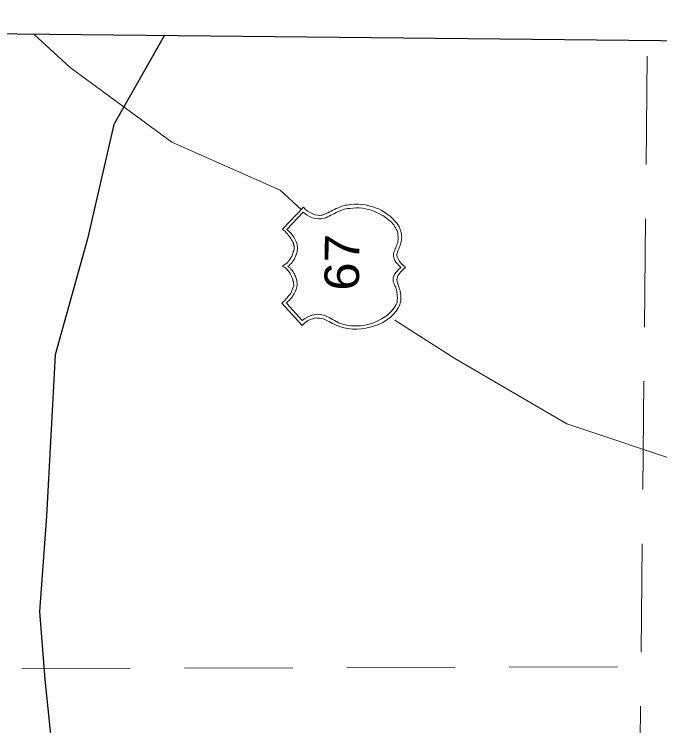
# Model space of a CAD drawing. Extents: x 2356576 to 2377878, y 6966390 to 6990634.
# Drawn here: x 2365982.5 to 2366109.4, y 6969120 to 6969259.9 of the extents above; entities that cross this region are included whole.
import ezdxf

# ---------------------------------------------------------------- set-up
doc = ezdxf.new("R2010")
doc.units = 0
doc.header["$LTSCALE"] = 7.1
doc.linetypes.add('MEDIUM_DASHED', pattern=[4.5, 3, -1.5])
doc.layers.add('19', color=7, linetype='Continuous', lineweight=13)
doc.layers.add('8', color=7, linetype='Continuous', lineweight=13)

msp = doc.modelspace()

# ---------------------------------------------------------------- linework, layer by layer
at = {"layer": '19', "linetype": 'MEDIUM_DASHED'}
for p, q in [((2366100.797, 6968655.28), (2366107.007, 6969254.676)), ((2365728.404, 6969130.515), (2366103.06, 6969131.614))]:
    msp.add_line(p, q, dxfattribs=at)
at = {"layer": '19'}
msp.add_line((2366034.755, 6969225.33), (2366038.887, 6969221.475), dxfattribs=at)
at = {"layer": '19', "lineweight": 25}
for points in [[(2365597.072, 6968660.498), (2366217.375, 6968654.072), (2366223.585, 6969253.468), (2365603.282, 6969259.894)], [(2366011.996, 6969255.66), (2366002.067, 6969238.242), (2365996.913, 6969215.73), (2365990.557, 6969192.935), (2365988.816, 6969161.211), (2365987.454, 6969142.5), (2365988.484, 6969129.141), (2365990.827, 6969106.283), (2365990.663, 6969090.412), (2365991.32, 6969078.497)]]:
    msp.add_lwpolyline(points, dxfattribs=at)
at = {"layer": '19'}
for points in [[(2365986.377, 6969255.925), (2365993.45, 6969249.432), (2366013.459, 6969234.732), (2366034.755, 6969225.33)], [(2366039.1, 6969198.732), (2366035.125, 6969203.125), (2366035.399, 6969203.363), (2366035.67, 6969203.6), (2366035.885, 6969203.866), (2366036.127, 6969204.103), (2366036.31, 6969204.341), (2366036.492, 6969204.611), (2366036.675, 6969204.817), (2366036.857, 6969205.088), (2366037.008, 6969205.326), (2366037.102, 6969205.565), (2366037.225, 6969205.832), (2366037.288, 6969206.071), (2366037.378, 6969206.342), (2366037.441, 6969206.55), (2366037.443, 6969206.822), (2366037.418, 6969207.09), (2366037.388, 6969207.27), (2366037.302, 6969207.483), (2366037.273, 6969207.723), (2366037.215, 6969207.964), (2366037.098, 6969208.205), (2366037.012, 6969208.414), (2366036.894, 6969208.655), (2366036.777, 6969208.897), (2366036.599, 6969209.138), (2366036.449, 6969209.352), (2366036.244, 6969209.562), (2366036.126, 6969209.775), (2366035.888, 6969209.958), (2366035.677, 6969210.108), (2366035.439, 6969210.231), (2366035.2, 6969210.353), (2366035.441, 6969210.503), (2366035.683, 6969210.68), (2366035.925, 6969210.826), (2366036.139, 6969211.035), (2366036.349, 6969211.213), (2366036.503, 6969211.452), (2366036.685, 6969211.658), (2366036.836, 6969211.896), (2366036.958, 6969212.135), (2366037.113, 6969212.373), (2366037.204, 6969212.644), (2366037.298, 6969212.883), (2366037.361, 6969213.183), (2366037.451, 6969213.39), (2366037.514, 6969213.689), (2366037.517, 6969213.961), (2366037.519, 6969214.169), (2366037.522, 6969214.409), (2366037.436, 6969214.622), (2366037.379, 6969214.891), (2366037.261, 6969215.104), (2366037.172, 6969215.345), (2366037.026, 6969215.554), (2366036.908, 6969215.796), (2366036.73, 6969216.009), (2366036.553, 6969216.279), (2366036.375, 6969216.493), (2366036.198, 6969216.735), (2366035.96, 6969216.945), (2366035.751, 6969217.22), (2366035.513, 6969217.402), (2366035.275, 6969217.645), (2366039.34, 6969221.951), (2366039.728, 6969221.559), (2366040.172, 6969221.162), (2366040.681, 6969220.889), (2366041.187, 6969220.672), (2366041.697, 6969220.458), (2366042.176, 6969220.393), (2366042.564, 6969220.357), (2366042.836, 6969220.386), (2366043.076, 6969220.412), (2366043.318, 6969220.529), (2366043.586, 6969220.587), (2366043.86, 6969220.736), (2366044.161, 6969220.881), (2366044.463, 6969221.03), (2366044.792, 6969221.174), (2366045.154, 6969221.35), (2366045.488, 6969221.527), (2366045.818, 6969221.704), (2366046.211, 6969221.852), (2366046.541, 6969221.996), (2366046.903, 6969222.144), (2366047.235, 6969222.229), (2366047.565, 6969222.346), (2366047.925, 6969222.374), (2366048.678, 6969222.486), (2366049.427, 6969222.538), (2366050.119, 6969222.531), (2366050.838, 6969222.464), (2366051.525, 6969222.397), (2366052.216, 6969222.237), (2366052.874, 6969222.083), (2366053.532, 6969221.864), (2366054.157, 6969221.617), (2366054.754, 6969221.311)], [(2366055.79, 6969219.74), (2366055.461, 6969219.984), (2366055.075, 6969220.26), (2366054.658, 6969220.472), (2366054.208, 6969220.717), (2366053.73, 6969220.934), (2366053.225, 6969221.147), (2366052.687, 6969221.364), (2366052.148, 6969221.518), (2366051.55, 6969221.644), (2366050.951, 6969221.742), (2366050.351, 6969221.809), (2366049.719, 6969221.815), (2366049.059, 6969221.79), (2366048.49, 6969221.736), (2366047.95, 6969221.682), (2366047.469, 6969221.567), (2366047.015, 6969221.423), (2366046.594, 6969221.276), (2366046.172, 6969221.1), (2366045.81, 6969220.924), (2366045.448, 6969220.719), (2366045.086, 6969220.511), (2366044.756, 6969220.367), (2366044.422, 6969220.19), (2366044.093, 6969220.041), (2366043.759, 6969219.897), (2366043.43, 6969219.808), (2366043.129, 6969219.723), (2366042.769, 6969219.667), (2366042.349, 6969219.671), (2366041.869, 6969219.736), (2366041.418, 6969219.829), (2366040.972, 6969219.954), (2366040.521, 6969220.138), (2366040.104, 6969220.415), (2366039.719, 6969220.687), (2366039.33, 6969220.991), (2366036.115, 6969217.604), (2366036.325, 6969217.394), (2366036.531, 6969217.212), (2366036.769, 6969216.997), (2366036.947, 6969216.787), (2366037.124, 6969216.545), (2366037.302, 6969216.304), (2366037.451, 6969216.062), (2366037.597, 6969215.82), (2366037.714, 6969215.547), (2366037.863, 6969215.306), (2366037.98, 6969215.036), (2366038.038, 6969214.824), (2366038.095, 6969214.555), (2366038.121, 6969214.343), (2366038.179, 6969214.162), (2366038.177, 6969213.954), (2366038.175, 6969213.742), (2366038.144, 6969213.475), (2366038.11, 6969213.235), (2366038.079, 6969212.995), (2366037.984, 6969212.724), (2366037.894, 6969212.517), (2366037.8, 6969212.246), (2366037.677, 6969212.007), (2366037.587, 6969211.8), (2366037.432, 6969211.502), (2366037.282, 6969211.323), (2366037.128, 6969211.113), (2366036.945, 6969210.875), (2366036.736, 6969210.729), (2366036.554, 6969210.519), (2366036.28, 6969210.342), (2366036.518, 6969210.159), (2366036.728, 6969210.009), (2366036.906, 6969209.795), (2366037.052, 6969209.614), (2366037.202, 6969209.432), (2366037.32, 6969209.251), (2366037.466, 6969209.009), (2366037.616, 6969208.86), (2366037.674, 6969208.619), (2366037.792, 6969208.406), (2366037.85, 6969208.197), (2366037.935, 6969207.985), (2366037.965, 6969207.776), (2366038.051, 6969207.535), (2366038.081, 6969207.323), (2366038.106, 6969207.115), (2366038.136, 6969206.874), (2366038.133, 6969206.574), (2366038.07, 6969206.335), (2366038.007, 6969206.036), (2366037.912, 6969205.765), (2366037.789, 6969205.466), (2366037.666, 6969205.167), (2366037.516, 6969204.961), (2366037.361, 6969204.662), (2366037.21, 6969204.392), (2366037.028, 6969204.154), (2366036.814, 6969203.948), (2366036.631, 6969203.678), (2366036.389, 6969203.472)], [(2366054.754, 6969221.311), (2366055.323, 6969220.977), (2366055.859, 6969220.612), (2366056.395, 6969220.214), (2366056.898, 6969219.729), (2366057.345, 6969219.244), (2366057.788, 6969218.731), (2366057.997, 6969218.429), (2366058.174, 6969218.127), (2366058.318, 6969217.826), (2366058.407, 6969217.525), (2366058.525, 6969217.252), (2366058.581, 6969216.951), (2366058.638, 6969216.623), (2366058.663, 6969216.35), (2366058.692, 6969216.05), (2366058.657, 6969215.75), (2366058.654, 6969215.482), (2366058.591, 6969215.211), (2366058.5, 6969214.912), (2366058.466, 6969214.672), (2366058.375, 6969214.433), (2366058.281, 6969214.194), (2366058.19, 6969213.955), (2366058.096, 6969213.748), (2366057.974, 6969213.537), (2366057.912, 6969213.33), (2366057.85, 6969213.119), (2366057.787, 6969212.879), (2366057.757, 6969212.671), (2366057.755, 6969212.431), (2366057.812, 6969212.191), (2366057.898, 6969211.95), (2366058.047, 6969211.676), (2366058.192, 6969211.435), (2366058.429, 6969211.104), (2366058.666, 6969210.802), (2366059.023, 6969210.498), (2366059.41, 6969210.102), (2366059.047, 6969209.778), (2366058.744, 6969209.449), (2366058.441, 6969209.184), (2366058.258, 6969208.914), (2366058.076, 6969208.676), (2366057.921, 6969208.438), (2366057.859, 6969208.23), (2366057.769, 6969208.019), (2366057.735, 6969207.839), (2366057.733, 6969207.631), (2366057.763, 6969207.479), (2366057.821, 6969207.271), (2366057.847, 6969207.09), (2366057.905, 6969206.91), (2366057.995, 6969206.697), (2366058.053, 6969206.488), (2366058.139, 6969206.335), (2366058.197, 6969206.095), (2366058.286, 6969205.854), (2366058.372, 6969205.613), (2366058.401, 6969205.344), (2366058.459, 6969205.104), (2366058.516, 6969204.803), (2366058.541, 6969204.563), (2366058.538, 6969204.263), (2366058.535, 6969204.023), (2366058.532, 6969203.723), (2366058.501, 6969203.391), (2366058.406, 6969203.124), (2366058.343, 6969202.825), (2366058.22, 6969202.526), (2366058.069, 6969202.228), (2366057.61, 6969201.54), (2366057.035, 6969200.886), (2366056.397, 6969200.293), (2366055.703, 6969199.76), (2366054.946, 6969199.288), (2366054.194, 6969198.908), (2366053.351, 6969198.616), (2366052.476, 6969198.353), (2366051.635, 6969198.182), (2366050.765, 6969198.043), (2366049.865, 6969197.992), (2366048.993, 6969198.001), (2366048.094, 6969198.099), (2366047.287, 6969198.259), (2366046.45, 6969198.508), (2366045.673, 6969198.816), (2366045.374, 6969198.939), (2366045.076, 6969199.09), (2366044.746, 6969199.274), (2366044.42, 6969199.489), (2366044.061, 6969199.641), (2366043.703, 6969199.824), (2366043.313, 6969200.008), (2366042.926, 6969200.072), (2366042.507, 6969200.169), (2366042.055, 6969200.173), (2366041.635, 6969200.178), (2366041.153, 6969200.031), (2366040.672, 6969199.888), (2366040.129, 6969199.593)], [(2366035.997, 6969203.116), (2366039.109, 6969199.664), (2366039.625, 6969200.047), (2366040.108, 6969200.314), (2366040.559, 6969200.549), (2366040.98, 6969200.725), (2366041.433, 6969200.808), (2366041.822, 6969200.896), (2366042.183, 6969200.952), (2366042.574, 6969200.888), (2366042.961, 6969200.792), (2366043.321, 6969200.728), (2366043.711, 6969200.604), (2366044.069, 6969200.421), (2366044.396, 6969200.269), (2366044.754, 6969200.085), (2366045.084, 6969199.87), (2366045.442, 6969199.658), (2366046.245, 6969199.258), (2366047.083, 6969198.981), (2366047.892, 6969198.761), (2366048.759, 6969198.664), (2366049.659, 6969198.623), (2366050.559, 6969198.645), (2366051.433, 6969198.784), (2366052.275, 6969198.988), (2366053.146, 6969199.247), (2366053.961, 6969199.598), (2366054.745, 6969199.982), (2366055.47, 6969200.455), (2366056.076, 6969200.956), (2366056.709, 6969201.522), (2366057.196, 6969202.145), (2366057.623, 6969202.8), (2366057.656, 6969202.952), (2366057.746, 6969203.099), (2366057.808, 6969203.31), (2366057.811, 6969203.55), (2366057.812, 6969203.73), (2366057.847, 6969203.97), (2366057.849, 6969204.21), (2366057.82, 6969204.45), (2366057.823, 6969204.718), (2366057.825, 6969204.958), (2366057.74, 6969205.199), (2366057.71, 6969205.44), (2366057.685, 6969205.68), (2366057.595, 6969205.893), (2366057.537, 6969206.101), (2366057.479, 6969206.282), (2366057.361, 6969206.495), (2366057.275, 6969206.676), (2366057.185, 6969206.857), (2366057.127, 6969207.038), (2366057.041, 6969207.279), (2366057.011, 6969207.427), (2366056.985, 6969207.639), (2366056.987, 6969207.847), (2366057.017, 6969208.059), (2366057.08, 6969208.358), (2366057.174, 6969208.565), (2366057.357, 6969208.803), (2366057.508, 6969209.102), (2366057.811, 6969209.399), (2366058.115, 6969209.756), (2366058.51, 6969210.084), (2366058.095, 6969210.508), (2366057.798, 6969210.871), (2366057.529, 6969211.174), (2366057.325, 6969211.504), (2366057.208, 6969211.805), (2366057.118, 6969212.046), (2366057.061, 6969212.319), (2366057.064, 6969212.587), (2366057.099, 6969212.826), (2366057.129, 6969213.038), (2366057.223, 6969213.277), (2366057.314, 6969213.516), (2366057.408, 6969213.755), (2366057.53, 6969213.962), (2366057.621, 6969214.233), (2366057.744, 6969214.5), (2366057.807, 6969214.771), (2366057.93, 6969215.038), (2366057.933, 6969215.338), (2366057.967, 6969215.609), (2366057.999, 6969215.909), (2366057.974, 6969216.209), (2366057.944, 6969216.478), (2366057.92, 6969216.778), (2366057.83, 6969217.051), (2366057.773, 6969217.352), (2366057.596, 6969217.621), (2366057.479, 6969217.923), (2366057.302, 6969218.164), (2366057.125, 6969218.466), (2366056.888, 6969218.741), (2366056.651, 6969219.011), (2366056.413, 6969219.226), (2366056.087, 6969219.469), (2366055.79, 6969219.74)], [(2366036.389, 6969203.472), (2366036.179, 6969203.294), (2366035.997, 6969203.116)], [(2366040.129, 6969199.593), (2366039.617, 6969199.239), (2366039.1, 6969198.732)], [(2366057.323, 6969199.743), (2366069.126, 6969192.209), (2366091.194, 6969179.379), (2366116.101, 6969171.021), (2366135.168, 6969166.623), (2366152.425, 6969144.183), (2366165.834, 6969143.864), (2366178.148, 6969121.955), (2366189.725, 6969104.283), (2366199.135, 6969082.764), (2366204.465, 6969052.823), (2366210.021, 6969027.324), (2366216.934, 6968999.531), (2366220.78, 6968982.778)]]:
    msp.add_lwpolyline(points, dxfattribs=at)
at = {"layer": '8', "linetype": 'MEDIUM_DASHED'}
for p, q in [((2366100.797, 6968655.28), (2366107.007, 6969254.676)), ((2365728.404, 6969130.515), (2366103.06, 6969131.614))]:
    msp.add_line(p, q, dxfattribs=at)
at = {"layer": '8'}
msp.add_line((2366034.755, 6969225.33), (2366038.887, 6969221.475), dxfattribs=at)
at = {"layer": '8', "lineweight": 25}
for points in [[(2365597.072, 6968660.498), (2366217.375, 6968654.072), (2366223.585, 6969253.468), (2365603.282, 6969259.894)], [(2366011.996, 6969255.66), (2366002.067, 6969238.242), (2365996.913, 6969215.73), (2365990.557, 6969192.935), (2365988.816, 6969161.211), (2365987.454, 6969142.5), (2365988.484, 6969129.141), (2365990.827, 6969106.283), (2365990.663, 6969090.412), (2365991.32, 6969078.497)]]:
    msp.add_lwpolyline(points, dxfattribs=at)
at = {"layer": '8'}
for points in [[(2365986.377, 6969255.925), (2365993.45, 6969249.432), (2366013.459, 6969234.732), (2366034.755, 6969225.33)], [(2366039.1, 6969198.732), (2366035.125, 6969203.125), (2366035.399, 6969203.363), (2366035.67, 6969203.6), (2366035.885, 6969203.866), (2366036.127, 6969204.103), (2366036.31, 6969204.341), (2366036.492, 6969204.611), (2366036.675, 6969204.817), (2366036.857, 6969205.088), (2366037.008, 6969205.326), (2366037.102, 6969205.565), (2366037.225, 6969205.832), (2366037.288, 6969206.071), (2366037.378, 6969206.342), (2366037.441, 6969206.55), (2366037.443, 6969206.822), (2366037.418, 6969207.09), (2366037.388, 6969207.27), (2366037.302, 6969207.483), (2366037.273, 6969207.723), (2366037.215, 6969207.964), (2366037.098, 6969208.205), (2366037.012, 6969208.414), (2366036.894, 6969208.655), (2366036.777, 6969208.897), (2366036.599, 6969209.138), (2366036.449, 6969209.352), (2366036.244, 6969209.562), (2366036.126, 6969209.775), (2366035.888, 6969209.958), (2366035.677, 6969210.108), (2366035.439, 6969210.231), (2366035.2, 6969210.353), (2366035.441, 6969210.503), (2366035.683, 6969210.68), (2366035.925, 6969210.826), (2366036.139, 6969211.035), (2366036.349, 6969211.213), (2366036.503, 6969211.452), (2366036.685, 6969211.658), (2366036.836, 6969211.896), (2366036.958, 6969212.135), (2366037.113, 6969212.373), (2366037.204, 6969212.644), (2366037.298, 6969212.883), (2366037.361, 6969213.183), (2366037.451, 6969213.39), (2366037.514, 6969213.689), (2366037.517, 6969213.961), (2366037.519, 6969214.169), (2366037.522, 6969214.409), (2366037.436, 6969214.622), (2366037.379, 6969214.891), (2366037.261, 6969215.104), (2366037.172, 6969215.345), (2366037.026, 6969215.554), (2366036.908, 6969215.796), (2366036.73, 6969216.009), (2366036.553, 6969216.279), (2366036.375, 6969216.493), (2366036.198, 6969216.735), (2366035.96, 6969216.945), (2366035.751, 6969217.22), (2366035.513, 6969217.402), (2366035.275, 6969217.645), (2366039.34, 6969221.951), (2366039.728, 6969221.559), (2366040.172, 6969221.162), (2366040.681, 6969220.889), (2366041.187, 6969220.672), (2366041.697, 6969220.458), (2366042.176, 6969220.393), (2366042.564, 6969220.357), (2366042.836, 6969220.386), (2366043.076, 6969220.412), (2366043.318, 6969220.529), (2366043.586, 6969220.587), (2366043.86, 6969220.736), (2366044.161, 6969220.881), (2366044.463, 6969221.03), (2366044.792, 6969221.174), (2366045.154, 6969221.35), (2366045.488, 6969221.527), (2366045.818, 6969221.704), (2366046.211, 6969221.852), (2366046.541, 6969221.996), (2366046.903, 6969222.144), (2366047.235, 6969222.229), (2366047.565, 6969222.346), (2366047.925, 6969222.374), (2366048.678, 6969222.486), (2366049.427, 6969222.538), (2366050.119, 6969222.531), (2366050.838, 6969222.464), (2366051.525, 6969222.397), (2366052.216, 6969222.237), (2366052.874, 6969222.083), (2366053.532, 6969221.864), (2366054.157, 6969221.617), (2366054.754, 6969221.311)], [(2366055.79, 6969219.74), (2366055.461, 6969219.984), (2366055.075, 6969220.26), (2366054.658, 6969220.472), (2366054.208, 6969220.717), (2366053.73, 6969220.934), (2366053.225, 6969221.147), (2366052.687, 6969221.364), (2366052.148, 6969221.518), (2366051.55, 6969221.644), (2366050.951, 6969221.742), (2366050.351, 6969221.809), (2366049.719, 6969221.815), (2366049.059, 6969221.79), (2366048.49, 6969221.736), (2366047.95, 6969221.682), (2366047.469, 6969221.567), (2366047.015, 6969221.423), (2366046.594, 6969221.276), (2366046.172, 6969221.1), (2366045.81, 6969220.924), (2366045.448, 6969220.719), (2366045.086, 6969220.511), (2366044.756, 6969220.367), (2366044.422, 6969220.19), (2366044.093, 6969220.041), (2366043.759, 6969219.897), (2366043.43, 6969219.808), (2366043.129, 6969219.723), (2366042.769, 6969219.667), (2366042.349, 6969219.671), (2366041.869, 6969219.736), (2366041.418, 6969219.829), (2366040.972, 6969219.954), (2366040.521, 6969220.138), (2366040.104, 6969220.415), (2366039.719, 6969220.687), (2366039.33, 6969220.991), (2366036.115, 6969217.604), (2366036.325, 6969217.394), (2366036.531, 6969217.212), (2366036.769, 6969216.997), (2366036.947, 6969216.787), (2366037.124, 6969216.545), (2366037.302, 6969216.304), (2366037.451, 6969216.062), (2366037.597, 6969215.82), (2366037.714, 6969215.547), (2366037.863, 6969215.306), (2366037.98, 6969215.036), (2366038.038, 6969214.824), (2366038.095, 6969214.555), (2366038.121, 6969214.343), (2366038.179, 6969214.162), (2366038.177, 6969213.954), (2366038.175, 6969213.742), (2366038.144, 6969213.475), (2366038.11, 6969213.235), (2366038.079, 6969212.995), (2366037.984, 6969212.724), (2366037.894, 6969212.517), (2366037.8, 6969212.246), (2366037.677, 6969212.007), (2366037.587, 6969211.8), (2366037.432, 6969211.502), (2366037.282, 6969211.323), (2366037.128, 6969211.113), (2366036.945, 6969210.875), (2366036.736, 6969210.729), (2366036.554, 6969210.519), (2366036.28, 6969210.342), (2366036.518, 6969210.159), (2366036.728, 6969210.009), (2366036.906, 6969209.795), (2366037.052, 6969209.614), (2366037.202, 6969209.432), (2366037.32, 6969209.251), (2366037.466, 6969209.009), (2366037.616, 6969208.86), (2366037.674, 6969208.619), (2366037.792, 6969208.406), (2366037.85, 6969208.197), (2366037.935, 6969207.985), (2366037.965, 6969207.776), (2366038.051, 6969207.535), (2366038.081, 6969207.323), (2366038.106, 6969207.115), (2366038.136, 6969206.874), (2366038.133, 6969206.574), (2366038.07, 6969206.335), (2366038.007, 6969206.036), (2366037.912, 6969205.765), (2366037.789, 6969205.466), (2366037.666, 6969205.167), (2366037.516, 6969204.961), (2366037.361, 6969204.662), (2366037.21, 6969204.392), (2366037.028, 6969204.154), (2366036.814, 6969203.948), (2366036.631, 6969203.678), (2366036.389, 6969203.472)], [(2366054.754, 6969221.311), (2366055.323, 6969220.977), (2366055.859, 6969220.612), (2366056.395, 6969220.214), (2366056.898, 6969219.729), (2366057.345, 6969219.244), (2366057.788, 6969218.731), (2366057.997, 6969218.429), (2366058.174, 6969218.127), (2366058.318, 6969217.826), (2366058.407, 6969217.525), (2366058.525, 6969217.252), (2366058.581, 6969216.951), (2366058.638, 6969216.623), (2366058.663, 6969216.35), (2366058.692, 6969216.05), (2366058.657, 6969215.75), (2366058.654, 6969215.482), (2366058.591, 6969215.211), (2366058.5, 6969214.912), (2366058.466, 6969214.672), (2366058.375, 6969214.433), (2366058.281, 6969214.194), (2366058.19, 6969213.955), (2366058.096, 6969213.748), (2366057.974, 6969213.537), (2366057.912, 6969213.33), (2366057.85, 6969213.119), (2366057.787, 6969212.879), (2366057.757, 6969212.671), (2366057.755, 6969212.431), (2366057.812, 6969212.191), (2366057.898, 6969211.95), (2366058.047, 6969211.676), (2366058.192, 6969211.435), (2366058.429, 6969211.104), (2366058.666, 6969210.802), (2366059.023, 6969210.498), (2366059.41, 6969210.102), (2366059.047, 6969209.778), (2366058.744, 6969209.449), (2366058.441, 6969209.184), (2366058.258, 6969208.914), (2366058.076, 6969208.676), (2366057.921, 6969208.438), (2366057.859, 6969208.23), (2366057.769, 6969208.019), (2366057.735, 6969207.839), (2366057.733, 6969207.631), (2366057.763, 6969207.479), (2366057.821, 6969207.271), (2366057.847, 6969207.09), (2366057.905, 6969206.91), (2366057.995, 6969206.697), (2366058.053, 6969206.488), (2366058.139, 6969206.335), (2366058.197, 6969206.095), (2366058.286, 6969205.854), (2366058.372, 6969205.613), (2366058.401, 6969205.344), (2366058.459, 6969205.104), (2366058.516, 6969204.803), (2366058.541, 6969204.563), (2366058.538, 6969204.263), (2366058.535, 6969204.023), (2366058.532, 6969203.723), (2366058.501, 6969203.391), (2366058.406, 6969203.124), (2366058.343, 6969202.825), (2366058.22, 6969202.526), (2366058.069, 6969202.228), (2366057.61, 6969201.54), (2366057.035, 6969200.886), (2366056.397, 6969200.293), (2366055.703, 6969199.76), (2366054.946, 6969199.288), (2366054.194, 6969198.908), (2366053.351, 6969198.616), (2366052.476, 6969198.353), (2366051.635, 6969198.182), (2366050.765, 6969198.043), (2366049.865, 6969197.992), (2366048.993, 6969198.001), (2366048.094, 6969198.099), (2366047.287, 6969198.259), (2366046.45, 6969198.508), (2366045.673, 6969198.816), (2366045.374, 6969198.939), (2366045.076, 6969199.09), (2366044.746, 6969199.274), (2366044.42, 6969199.489), (2366044.061, 6969199.641), (2366043.703, 6969199.824), (2366043.313, 6969200.008), (2366042.926, 6969200.072), (2366042.507, 6969200.169), (2366042.055, 6969200.173), (2366041.635, 6969200.178), (2366041.153, 6969200.031), (2366040.672, 6969199.888), (2366040.129, 6969199.593)], [(2366035.997, 6969203.116), (2366039.109, 6969199.664), (2366039.625, 6969200.047), (2366040.108, 6969200.314), (2366040.559, 6969200.549), (2366040.98, 6969200.725), (2366041.433, 6969200.808), (2366041.822, 6969200.896), (2366042.183, 6969200.952), (2366042.574, 6969200.888), (2366042.961, 6969200.792), (2366043.321, 6969200.728), (2366043.711, 6969200.604), (2366044.069, 6969200.421), (2366044.396, 6969200.269), (2366044.754, 6969200.085), (2366045.084, 6969199.87), (2366045.442, 6969199.658), (2366046.245, 6969199.258), (2366047.083, 6969198.981), (2366047.892, 6969198.761), (2366048.759, 6969198.664), (2366049.659, 6969198.623), (2366050.559, 6969198.645), (2366051.433, 6969198.784), (2366052.275, 6969198.988), (2366053.146, 6969199.247), (2366053.961, 6969199.598), (2366054.745, 6969199.982), (2366055.47, 6969200.455), (2366056.076, 6969200.956), (2366056.709, 6969201.522), (2366057.196, 6969202.145), (2366057.623, 6969202.8), (2366057.656, 6969202.952), (2366057.746, 6969203.099), (2366057.808, 6969203.31), (2366057.811, 6969203.55), (2366057.812, 6969203.73), (2366057.847, 6969203.97), (2366057.849, 6969204.21), (2366057.82, 6969204.45), (2366057.823, 6969204.718), (2366057.825, 6969204.958), (2366057.74, 6969205.199), (2366057.71, 6969205.44), (2366057.685, 6969205.68), (2366057.595, 6969205.893), (2366057.537, 6969206.101), (2366057.479, 6969206.282), (2366057.361, 6969206.495), (2366057.275, 6969206.676), (2366057.185, 6969206.857), (2366057.127, 6969207.038), (2366057.041, 6969207.279), (2366057.011, 6969207.427), (2366056.985, 6969207.639), (2366056.987, 6969207.847), (2366057.017, 6969208.059), (2366057.08, 6969208.358), (2366057.174, 6969208.565), (2366057.357, 6969208.803), (2366057.508, 6969209.102), (2366057.811, 6969209.399), (2366058.115, 6969209.756), (2366058.51, 6969210.084), (2366058.095, 6969210.508), (2366057.798, 6969210.871), (2366057.529, 6969211.174), (2366057.325, 6969211.504), (2366057.208, 6969211.805), (2366057.118, 6969212.046), (2366057.061, 6969212.319), (2366057.064, 6969212.587), (2366057.099, 6969212.826), (2366057.129, 6969213.038), (2366057.223, 6969213.277), (2366057.314, 6969213.516), (2366057.408, 6969213.755), (2366057.53, 6969213.962), (2366057.621, 6969214.233), (2366057.744, 6969214.5), (2366057.807, 6969214.771), (2366057.93, 6969215.038), (2366057.933, 6969215.338), (2366057.967, 6969215.609), (2366057.999, 6969215.909), (2366057.974, 6969216.209), (2366057.944, 6969216.478), (2366057.92, 6969216.778), (2366057.83, 6969217.051), (2366057.773, 6969217.352), (2366057.596, 6969217.621), (2366057.479, 6969217.923), (2366057.302, 6969218.164), (2366057.125, 6969218.466), (2366056.888, 6969218.741), (2366056.651, 6969219.011), (2366056.413, 6969219.226), (2366056.087, 6969219.469), (2366055.79, 6969219.74)], [(2366036.389, 6969203.472), (2366036.179, 6969203.294), (2366035.997, 6969203.116)], [(2366040.129, 6969199.593), (2366039.617, 6969199.239), (2366039.1, 6969198.732)], [(2366057.323, 6969199.743), (2366069.126, 6969192.209), (2366091.194, 6969179.379), (2366116.101, 6969171.021), (2366135.168, 6969166.623), (2366152.425, 6969144.183), (2366165.834, 6969143.864), (2366178.148, 6969121.955), (2366189.725, 6969104.283), (2366199.135, 6969082.764), (2366204.465, 6969052.823), (2366210.021, 6969027.324), (2366216.934, 6968999.531), (2366220.78, 6968982.778)]]:
    msp.add_lwpolyline(points, dxfattribs=at)

# ---------------------------------------------------------------- texts
at = {"layer": '19', "width": 1.1}
msp.add_text('67', height=6.798, rotation=89.406, dxfattribs=at).set_placement((2366050.27, 6969205.517))
at = {"layer": '8', "width": 1.1}
msp.add_text('67', height=6.798, rotation=89.406, dxfattribs=at).set_placement((2366050.27, 6969205.517))

doc.saveas('drawing.dxf')
